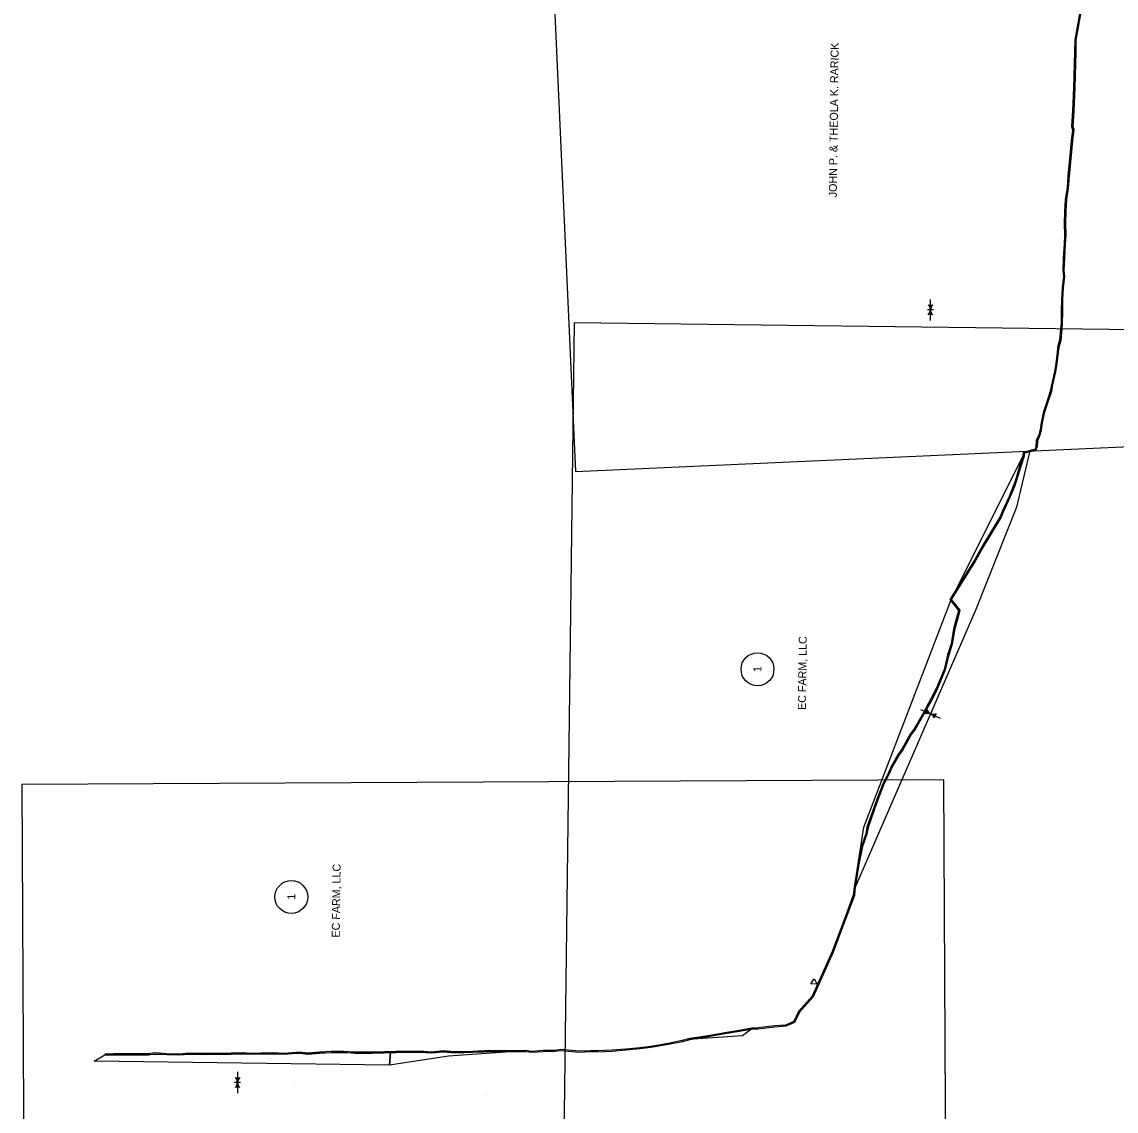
# Model space of a CAD drawing. Extents: x 20504422 to 20508365, y 7965199 to 7983597.
# Drawn here: x 20504752 to 20506611, y 7970508 to 7972359 of the extents above; entities that cross this region are included whole.
import ezdxf

# ---------------------------------------------------------------- set-up
doc = ezdxf.new("R2010")
doc.units = 0
for name, color, linetype in [('SurControl', 7, 'Continuous'), ('SurDikeDam', 7, 'Continuous'), ('SurLotCorner', 7, 'Continuous'), ('SurRipRap', 7, 'Continuous'), ('SurTopOfWater', 7, 'Continuous'), ('SurWetlands', 7, 'Continuous')]:
    doc.layers.add(name, color=color, linetype=linetype)

msp = doc.modelspace()

# ---------------------------------------------------------------- linework, layer by layer
at = {"layer": 'SurControl'}
for centre in [(20506001.5, 7971259), (20505209.6, 7970872.1)]:
    msp.add_circle(centre, 28, dxfattribs=at)
at = {"layer": 'SurDikeDam'}
for p, q in [((20506455.1, 7971626.3), (20506463.9, 7971630.2)), ((20506330.9, 7971378.9), (20506455.1, 7971626.3)), ((20506182, 7970990.7), (20506330.9, 7971378.9)), ((20506166, 7970884.9), (20506182, 7970990.7))]:
    msp.add_line(p, q, dxfattribs=at)
msp.add_lwpolyline([(20506463.9, 7971630.2), (20506441.3, 7971534.7), (20506372.6, 7971360.6), (20506166, 7970884.9)], dxfattribs=at)
for points in [[(20505883.9, 7970629.8), (20505991.3, 7970647.7), (20505975.9, 7970636.2)], [(20504874.6, 7970592.9), (20504892.8, 7970603.8), (20505377.9, 7970608.3), (20505376.2, 7970586.4)], [(20505376.2, 7970586.4), (20505377.9, 7970608.3), (20505597.9, 7970610), (20505476.5, 7970601.6)]]:
    msp.add_lwpolyline(points, close=True, dxfattribs=at)
at = {"layer": 'SurLotCorner'}
for p, q in [((20506295.3, 7971869.8), (20506295.5, 7971887.7)), ((20506300.4, 7971869.7), (20506290.2, 7971869.8)), ((20506295.3, 7971869.8), (20506295.1, 7971851.9)), ((20506295.6, 7971183.3), (20506279.2, 7971190.4)), ((20506297.6, 7971188), (20506293.6, 7971178.7)), ((20506295.6, 7971183.3), (20506312, 7971176.2)), ((20506092.2, 7970724.3), (20506097.6, 7970733.3)), ((20506102.7, 7970724.2), (20506092.2, 7970724.3)), ((20506097.6, 7970733.3), (20506102.7, 7970724.2)), ((20505118.2, 7970556.9), (20505118.5, 7970574.7)), ((20505123.3, 7970556.8), (20505113.2, 7970556.9)), ((20505118.2, 7970556.9), (20505118, 7970539))]:
    msp.add_line(p, q, dxfattribs=at)
for centre, radius, start, end in [((20506280.8, 7971868.4), 14.6, 5.3849, 43.1922), ((20506295.5, 7971889), 11.4, 248.6722, 289.8859), ((20506309.8, 7971868), 14.6, 135.366, 173.1732), ((20506280.8, 7971871.5), 14.6, 315.366, 353.1732), ((20506295.1, 7971850.6), 11.4, 68.6722, 109.8859), ((20506309.8, 7971871.1), 14.6, 185.3849, 223.1922), ((20506278, 7971191), 11.4, 315.9124, 357.1261), ((20506291.2, 7971169.4), 14.6, 72.6251, 110.4324), ((20506302.8, 7971196), 14.6, 202.6062, 240.4134), ((20506300, 7971197.2), 14.6, 252.6251, 290.4324), ((20506288.4, 7971170.6), 14.6, 22.6062, 60.4134), ((20506313.2, 7971175.7), 11.4, 135.9124, 177.1261), ((20505103.8, 7970558.6), 14.6, 315.366, 353.1732), ((20505103.7, 7970555.5), 14.6, 5.3849, 43.1922), ((20505118.5, 7970576), 11.4, 248.6722, 289.8859), ((20505132.7, 7970555.1), 14.6, 135.366, 173.1732), ((20505132.8, 7970558.2), 14.6, 185.3849, 223.1922), ((20505118, 7970537.7), 11.4, 68.6722, 109.8859)]:
    msp.add_arc(centre, radius, start, end, dxfattribs=at)
at = {"layer": 'SurRipRap'}
for points in [[(20505692.1, 7971595), (20507690.1, 7971685.2), (20507549.3, 7974806.4), (20505551.3, 7974716.3)], [(20505650.4, 7968713.3), (20507650.2, 7968688.1), (20507689.7, 7971822.9), (20505689.8, 7971848)]]:
    msp.add_lwpolyline(points, close=True, dxfattribs=at)
at = {"layer": 'SurTopOfWater'}
for p, q in [((20505216.9, 7970555.7), (20505216.9, 7970555.7)), ((20505542.2, 7970534.1), (20505542.2, 7970534.1))]:
    msp.add_line(p, q, dxfattribs=at)
for points in [[(20506551.2, 7972388.5), (20506540.5, 7972328.4), (20506540.2, 7972307.8), (20506538.6, 7972247.7), (20506536.8, 7972207.8), (20506535, 7972181.6), (20506536.8, 7972175.6), (20506534.4, 7972157.1), (20506529, 7972097.1), (20506527.5, 7972077.4), (20506524.4, 7972057.6), (20506523.1, 7972037.1), (20506522.6, 7972016.8), (20506523.2, 7971996.8), (20506522.4, 7971982.1), (20506521, 7971957.1), (20506520.2, 7971936.6), (20506521.1, 7971926.7), (20506518.9, 7971907.3), (20506517.9, 7971887), (20506517.5, 7971866.9), (20506517.2, 7971847), (20506516.4, 7971837.3), (20506514.8, 7971818.2), (20506511.8, 7971808.5), (20506510.4, 7971797.9), (20506508.2, 7971778.7), (20506505.9, 7971764.8), (20506500.7, 7971742.6), (20506498.7, 7971731.8), (20506492.8, 7971713.6), (20506486.7, 7971694.7), (20506482.7, 7971675.2), (20506481.6, 7971665.9), (20506479.2, 7971657.5), (20506475.2, 7971647.8), (20506474.4, 7971637.8), (20506473, 7971633), (20506452.9, 7971627.2), (20506452.4, 7971621.4), (20506447.3, 7971605.7), (20506439.3, 7971578.7), (20506436, 7971570.1), (20506429.1, 7971552.7), (20506416.9, 7971526.9), (20506413.7, 7971518.4), (20506399.1, 7971494.3), (20506384.6, 7971469.8), (20506370.5, 7971445.4), (20506351, 7971413.6), (20506328.4, 7971377.6), (20506343, 7971359.1), (20506341.3, 7971352.7), (20506334.5, 7971327.9), (20506330.5, 7971302.4), (20506324.4, 7971283.5), (20506318.6, 7971258.7), (20506305.6, 7971227.3), (20506296.8, 7971209.8), (20506282.2, 7971183.6), (20506267.7, 7971157.8), (20506261.5, 7971149.7), (20506246.6, 7971123.4), (20506240.4, 7971115), (20506228.6, 7971094.1), (20506224.5, 7971084.6), (20506214.6, 7971064.6), (20506202.3, 7971033.1), (20506187.5, 7970990.5), (20506185.3, 7970979.5), (20506178.1, 7970958.4), (20506171.4, 7970925), (20506165, 7970884.4), (20506164.2, 7970875.1), (20506150.3, 7970838), (20506128.2, 7970779.4), (20506094.2, 7970703.6), (20506071.4, 7970677.4), (20506063.1, 7970660.4), (20506049.1, 7970654.5), (20506030.9, 7970653), (20506002.7, 7970649.6), (20505991.8, 7970649.3), (20505970.3, 7970645.3), (20505949.3, 7970641.9), (20505918, 7970636.4), (20505886.4, 7970631.4), (20505873.4, 7970628), (20505849.7, 7970623.3), (20505820.3, 7970618.2), (20505801.8, 7970615.9), (20505777.8, 7970613.6), (20505754.8, 7970611.8), (20505729.5, 7970610.6), (20505717.1, 7970610.7), (20505698, 7970610), (20505667.7, 7970612.8), (20505657.3, 7970611.4), (20505637.6, 7970611.1), (20505618.1, 7970609.8), (20505608.3, 7970611.2), (20505582.4, 7970610.9), (20505558, 7970610.5), (20505547.9, 7970611.1), (20505537.5, 7970610.6), (20505517.5, 7970609.7), (20505488, 7970608.7), (20505467.8, 7970610.5), (20505447.7, 7970608.5), (20505428, 7970610.1), (20505387.6, 7970609.4), (20505347.7, 7970608.2), (20505318.1, 7970608.2), (20505298, 7970609.8), (20505277.5, 7970609.4), (20505257.3, 7970608.3), (20505237.8, 7970606.7), (20505228.2, 7970607.7), (20505217.6, 7970608.1), (20505197.5, 7970606.4), (20505177.8, 7970607), (20505157.6, 7970606.8), (20505137.9, 7970606.4), (20505127.9, 7970607), (20505107.6, 7970606.7), (20505067.7, 7970606.1), (20505037.5, 7970606.6), (20505017.5, 7970605.2), (20504998, 7970605.8), (20504977.4, 7970607.2), (20504967.1, 7970605.5), (20504947.7, 7970605.3), (20504927.7, 7970605.4), (20504907.5, 7970605.4), (20504897.6, 7970604.9), (20504892.8, 7970605.1)], [(20506553.2, 7972388.1), (20506542.5, 7972328.2), (20506542.2, 7972307.8), (20506540.6, 7972247.6), (20506538.8, 7972207.7), (20506537, 7972181.9), (20506538.8, 7972175.8), (20506536.4, 7972156.8), (20506531, 7972097), (20506529.5, 7972077.2), (20506526.4, 7972057.3), (20506525.1, 7972037.1), (20506524.6, 7972016.8), (20506525.2, 7971996.8), (20506524.4, 7971982), (20506523, 7971957), (20506522.2, 7971936.6), (20506523.1, 7971926.7), (20506520.9, 7971907.2), (20506519.9, 7971886.9), (20506519.5, 7971866.8), (20506519.2, 7971846.9), (20506518.4, 7971837.1), (20506516.8, 7971817.8), (20506513.8, 7971808.1), (20506512.4, 7971797.7), (20506510.1, 7971778.4), (20506507.8, 7971764.4), (20506502.7, 7971742.2), (20506500.7, 7971731.3), (20506494.7, 7971713), (20506488.6, 7971694.2), (20506484.7, 7971674.9), (20506483.6, 7971665.5), (20506481.1, 7971656.9), (20506477.2, 7971647.4), (20506476.4, 7971637.4), (20506474.6, 7971631.3), (20506454.8, 7971625.6), (20506454.3, 7971621), (20506449.2, 7971605.1), (20506441.2, 7971578), (20506437.9, 7971569.4), (20506431, 7971551.9), (20506418.7, 7971526.1), (20506415.5, 7971517.5), (20506400.8, 7971493.3), (20506386.3, 7971468.8), (20506372.2, 7971444.4), (20506352.7, 7971412.6), (20506330.8, 7971377.7), (20506345.2, 7971359.6), (20506343.3, 7971352.2), (20506336.5, 7971327.5), (20506332.4, 7971301.9), (20506326.3, 7971282.9), (20506320.5, 7971258.1), (20506307.5, 7971226.4), (20506298.6, 7971208.8), (20506284, 7971182.7), (20506269.4, 7971156.7), (20506263.2, 7971148.6), (20506248.3, 7971122.4), (20506242.1, 7971113.9), (20506230.4, 7971093.2), (20506226.4, 7971083.8), (20506216.4, 7971063.8), (20506204.2, 7971032.4), (20506189.4, 7970990), (20506187.3, 7970979), (20506180, 7970957.9), (20506173.3, 7970924.7), (20506167, 7970884.2), (20506166.1, 7970874.7), (20506152.2, 7970837.3), (20506130.1, 7970778.6), (20506095.9, 7970702.5), (20506073.1, 7970676.3), (20506064.6, 7970658.9), (20506049.6, 7970652.5), (20506031.1, 7970651), (20506002.9, 7970647.7), (20505992.1, 7970647.3), (20505970.7, 7970643.4), (20505949.7, 7970640), (20505918.3, 7970634.4), (20505886.8, 7970629.4), (20505873.8, 7970626.1), (20505850.1, 7970621.3), (20505820.6, 7970616.2), (20505802, 7970613.9), (20505778, 7970611.6), (20505754.9, 7970609.8), (20505729.5, 7970608.6), (20505717.2, 7970608.7), (20505698, 7970608), (20505667.8, 7970610.8), (20505657.5, 7970609.4), (20505637.6, 7970609.1), (20505618, 7970607.8), (20505608.2, 7970609.2), (20505582.4, 7970608.9), (20505558, 7970608.5), (20505547.9, 7970609.1), (20505537.6, 7970608.6), (20505517.6, 7970607.7), (20505487.9, 7970606.7), (20505467.8, 7970608.5), (20505447.7, 7970606.5), (20505428, 7970608.1), (20505387.7, 7970607.4), (20505347.7, 7970606.2), (20505318, 7970606.2), (20505297.9, 7970607.8), (20505277.6, 7970607.4), (20505257.4, 7970606.3), (20505237.8, 7970604.7), (20505228.1, 7970605.7), (20505217.6, 7970606), (20505197.6, 7970604.4), (20505177.8, 7970605), (20505157.6, 7970604.8), (20505137.8, 7970604.4), (20505127.9, 7970605), (20505107.6, 7970604.7), (20505067.7, 7970604.1), (20505037.6, 7970604.6), (20505017.6, 7970603.2), (20504997.9, 7970603.8), (20504977.5, 7970605.2), (20504967.2, 7970603.5), (20504947.7, 7970603.3), (20504927.7, 7970603.4), (20504907.5, 7970603.4), (20504897.6, 7970602.9), (20504892.8, 7970603.1)]]:
    msp.add_lwpolyline(points, dxfattribs=at)
msp.add_lwpolyline([(20504751.9, 7971063.2), (20504756.9, 7970063.3), (20506323.1, 7970071.2), (20506318, 7971071.2)], close=True, dxfattribs=at)
at = {"layer": 'SurWetlands'}
for p, q in [((20506455.1, 7971626.3), (20506463.9, 7971630.2)), ((20506330.9, 7971378.9), (20506455.1, 7971626.3)), ((20506182, 7970990.7), (20506330.9, 7971378.9)), ((20506166, 7970884.9), (20506182, 7970990.7)), ((20505883.9, 7970629.8), (20505991.3, 7970647.7)), ((20504892.8, 7970603.8), (20505377.9, 7970608.3)), ((20505376.2, 7970586.4), (20505377.9, 7970608.3)), ((20505377.9, 7970608.3), (20505597.9, 7970610)), ((20504874.6, 7970592.9), (20504892.8, 7970603.8))]:
    msp.add_line(p, q, dxfattribs=at)

# ---------------------------------------------------------------- texts
at = {"layer": 'SurControl'}
for s, p in [('JOHN P. & THEOLA K. RARICK', (20506136.3, 7972061.1)), ('EC FARM, LLC', (20506083.7, 7971189.9)), ('1', (20506008.2, 7971254.3)), ('EC FARM, LLC', (20505291.8, 7970803.1)), ('1', (20505216.3, 7970867.4))]:
    msp.add_text(s, height=13.6, rotation=89.2974, dxfattribs=at).set_placement(p)

doc.saveas('drawing.dxf')
